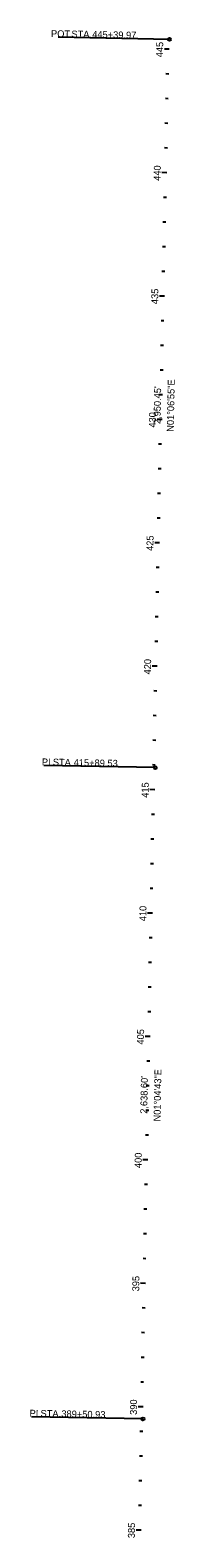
# Model space of a CAD drawing. Extents: x 1807668 to 1809726, y 297763 to 325145.
# Drawn here: x 1808372 to 1808955, y 319037 to 325145 of the extents above; entities that cross this region are included whole.
import ezdxf

# ---------------------------------------------------------------- set-up
doc = ezdxf.new("R2010")
doc.units = 0
for name, color, linetype in [('GE_P_Alignment_500_Bearings', 7, 'Continuous'), ('GE_P_Alignment_500_Cardinal_Points', 7, 'Continuous'), ('GE_P_Alignment_500_Distances', 7, 'Continuous'), ('GE_P_Alignment_500_Stations', 7, 'Continuous')]:
    doc.layers.add(name, color=color, linetype=linetype)

msp = doc.modelspace()

# ---------------------------------------------------------------- linework, layer by layer
at = {"layer": 'GE_P_Alignment_500_Cardinal_Points'}
for p, q in [((1808934.3, 325107.2), (1808484.4, 325115.9)), ((1808876.9, 322157.3), (1808427, 322166)), ((1808827.2, 319519.2), (1808377.3, 319527.6))]:
    msp.add_line(p, q, dxfattribs=at)
for centre in [(1808934.3, 325107.2), (1808876.9, 322157.3), (1808827.2, 319519.2)]:
    msp.add_circle(centre, 6, dxfattribs=at)
at = {"layer": 'GE_P_Alignment_500_Stations'}
for p, q in [((1808933.5, 325067.2), (1808913.5, 325067.6)), ((1808931.6, 324967.2), (1808919.6, 324967.5)), ((1808929.6, 324867.2), (1808917.7, 324867.5)), ((1808927.7, 324767.3), (1808915.7, 324767.5)), ((1808925.8, 324667.3), (1808913.8, 324667.5)), ((1808923.8, 324567.3), (1808903.8, 324567.7)), ((1808921.9, 324467.3), (1808909.9, 324467.6)), ((1808919.9, 324367.3), (1808907.9, 324367.6)), ((1808918, 324267.4), (1808906, 324267.6)), ((1808916, 324167.4), (1808904, 324167.6)), ((1808914.1, 324067.4), (1808894.1, 324067.8)), ((1808912.1, 323967.4), (1808900.1, 323967.7)), ((1808910.2, 323867.4), (1808898.2, 323867.7)), ((1808908.2, 323767.5), (1808896.2, 323767.7)), ((1808906.3, 323667.5), (1808894.3, 323667.7)), ((1808904.3, 323567.5), (1808884.3, 323567.9)), ((1808902.4, 323467.5), (1808890.4, 323467.7)), ((1808900.5, 323367.5), (1808888.5, 323367.8)), ((1808898.5, 323267.5), (1808886.5, 323267.8)), ((1808896.6, 323167.6), (1808884.6, 323167.8)), ((1808894.6, 323067.6), (1808874.6, 323068)), ((1808892.7, 322967.6), (1808880.7, 322967.8)), ((1808890.7, 322867.6), (1808878.7, 322867.9)), ((1808888.8, 322767.6), (1808876.8, 322767.9)), ((1808886.8, 322667.7), (1808874.8, 322667.9)), ((1808884.9, 322567.7), (1808864.9, 322568.1)), ((1808882.9, 322467.7), (1808870.9, 322467.9)), ((1808881, 322367.7), (1808869, 322368)), ((1808879, 322267.7), (1808867, 322268)), ((1808877.1, 322167.8), (1808865.1, 322168)), ((1808875.2, 322067.8), (1808855.2, 322068.2)), ((1808873.3, 321967.8), (1808861.3, 321968)), ((1808871.4, 321867.8), (1808859.4, 321868)), ((1808869.6, 321767.8), (1808857.6, 321768.1)), ((1808867.7, 321667.8), (1808855.7, 321668.1)), ((1808865.8, 321567.9), (1808845.8, 321568.2)), ((1808863.9, 321467.9), (1808851.9, 321468.1)), ((1808862, 321367.9), (1808850, 321368.1)), ((1808860.1, 321267.9), (1808848.1, 321268.1)), ((1808858.3, 321167.9), (1808846.3, 321168.2)), ((1808856.4, 321068), (1808836.4, 321068.3)), ((1808854.5, 320968), (1808842.5, 320968.2)), ((1808852.6, 320868), (1808840.6, 320868.2)), ((1808850.7, 320768), (1808838.7, 320768.2)), ((1808848.9, 320668), (1808836.9, 320668.2)), ((1808847, 320568), (1808827, 320568.4)), ((1808845.1, 320468.1), (1808833.1, 320468.3)), ((1808843.2, 320368.1), (1808831.2, 320368.3)), ((1808841.3, 320268.1), (1808829.3, 320268.3)), ((1808839.4, 320168.1), (1808827.4, 320168.3)), ((1808837.6, 320068.1), (1808817.6, 320068.5)), ((1808835.7, 319968.1), (1808823.7, 319968.4)), ((1808833.8, 319868.2), (1808821.8, 319868.4)), ((1808831.9, 319768.2), (1808819.9, 319768.4)), ((1808830, 319668.2), (1808818, 319668.4)), ((1808828.1, 319568.2), (1808808.1, 319568.6)), ((1808826.4, 319468.2), (1808814.4, 319468.4)), ((1808824.7, 319368.2), (1808812.7, 319368.4)), ((1808823, 319268.3), (1808811.1, 319268.5)), ((1808821.4, 319168.3), (1808809.4, 319168.5)), ((1808819.7, 319068.3), (1808799.7, 319068.6))]:
    msp.add_line(p, q, dxfattribs=at)

# ---------------------------------------------------------------- texts
at = {"layer": 'GE_P_Alignment_500_Bearings'}
for s, rotation, p in [('N01°06\'55"E', 88.88469, (1808951.4, 323517.7)), ('N01°04\'43"E', 88.92133, (1808897.9, 320723.7))]:
    msp.add_text(s, height=28, rotation=rotation, dxfattribs=at).set_placement(p)
at = {"layer": 'GE_P_Alignment_500_Cardinal_Points'}
for s, rotation, p in [('POT', 358.88469, (1808455.7, 325116.9)), (' STA. ', 358.88469, (1808527.7, 325115.5)), ('445+39.97', 358.88469, (1808622.2, 325113.7)), ('PI', 358.88469, (1808418.8, 322166.6)), (' STA. ', 358.88469, (1808452.7, 322166)), ('415+89.53', 358.88469, (1808547.2, 322164.1)), ('PI', 358.92133, (1808369.1, 319528.2)), (' STA. ', 358.92133, (1808403, 319527.6)), ('389+50.93', 358.92133, (1808497.5, 319525.8))]:
    msp.add_text(s, height=28, rotation=rotation, dxfattribs=at).set_placement(p)
at = {"layer": 'GE_P_Alignment_500_Distances'}
for s, rotation, p in [("2,950.45'", 88.88469, (1808897.8, 323548.9)), ("2,638.60'", 88.92133, (1808844.3, 320754.9))]:
    msp.add_text(s, height=28, rotation=rotation, dxfattribs=at).set_placement(p)
at = {"layer": 'GE_P_Alignment_500_Stations'}
for s, rotation, p in [('445', 88.88469, (1808907.9, 325034.7)), ('440', 88.88469, (1808898.2, 324534.3)), ('435', 88.88469, (1808888.4, 324034.8)), ('430', 88.88469, (1808878.7, 323534.5)), ('425', 88.88469, (1808869, 323035)), ('420', 88.88469, (1808859.2, 322534.7)), ('415', 88.92133, (1808849.6, 322035.2)), ('410', 88.92133, (1808840.2, 321534.9)), ('405', 88.92133, (1808830.8, 321035.4)), ('400', 88.92133, (1808821.3, 320535)), ('395', 88.92133, (1808811.9, 320035.6)), ('390', 88.92133, (1808802.5, 319535.2)), ('385', 89.04778, (1808794.2, 319035.7))]:
    msp.add_text(s, height=28, rotation=rotation, dxfattribs=at).set_placement(p)

doc.saveas('drawing.dxf')
